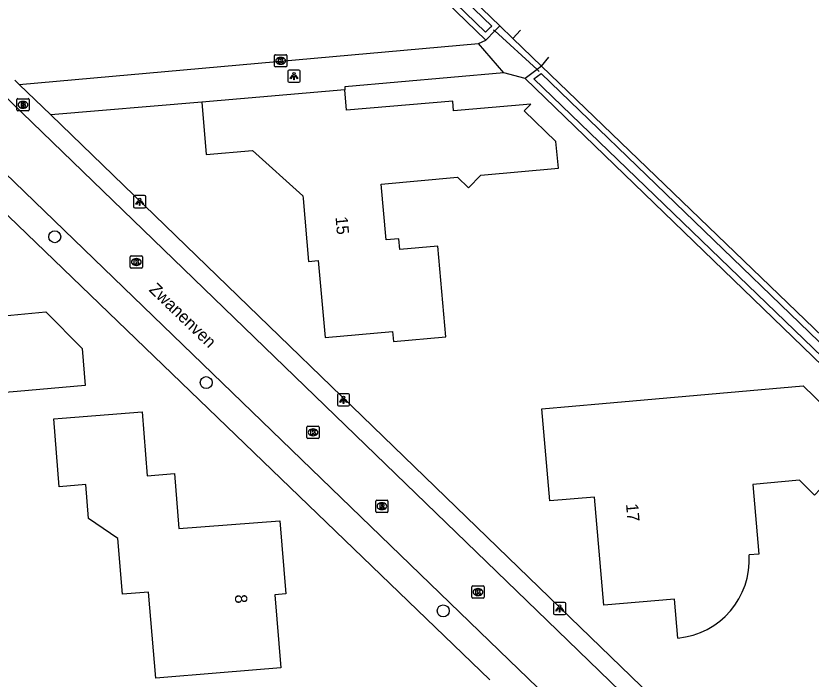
# Model space of a CAD drawing. Extents: x 163427 to 164190, y 380331 to 381641.
# Drawn here: x 164069.2 to 164134.4, y 381117.1 to 381171.6 of the extents above; entities that cross this region are included whole.
import ezdxf

# ---------------------------------------------------------------- set-up
doc = ezdxf.new("R2010")
doc.units = 0
for name, color, linetype in [('IMGEO_Boom', 7, 'Continuous'), ('IMGEO_Brandkraan', 7, 'Continuous'), ('IMGEO_Duiker', 7, 'Continuous'), ('IMGEO_Erf', 7, 'Continuous'), ('IMGEO_Grasland_overig', 7, 'Continuous'), ('IMGEO_Groenvoorziening', 7, 'Continuous'), ('IMGEO_Kolk', 7, 'Continuous'), ('IMGEO_Lichtpunt', 7, 'Continuous'), ('IMGEO_Openbare_ruimte_label', 7, 'Continuous'), ('IMGEO_Pand', 7, 'Continuous'), ('IMGEO_Pand_nummerreeks', 7, 'Continuous'), ('IMGEO_Rijbaan_lokaal_open', 7, 'Continuous'), ('IMGEO_Rioolput', 7, 'Continuous'), ('IMGEO_Voetpad_open', 7, 'Continuous'), ('IMGEO_Waterloop', 7, 'Continuous')]:
    doc.layers.add(name, color=color, linetype=linetype)

msp = doc.modelspace()

# ---------------------------------------------------------------- linework, layer by layer
at = {"layer": 'IMGEO_Boom'}
for centre in [(164072.345, 381153.442), (164084.77, 381141.476), (164104.218, 381122.747)]:
    msp.add_circle(centre, 0.489, dxfattribs=at)
at = {"layer": 'IMGEO_Brandkraan'}
for p, q in [((164069.234, 381163.847), (164069.234, 381164.699)), ((164069.309, 381164.773), (164070.161, 381164.773)), ((164069.722, 381164.553), (164069.747, 381164.553)), ((164070.235, 381164.699), (164070.235, 381163.847)), ((164070.161, 381163.773), (164069.309, 381163.773)), ((164069.745, 381163.993), (164069.72, 381163.993))]:
    msp.add_line(p, q, dxfattribs=at)
for points in [[(164069.234, 381163.847), (164069.234, 381164.699)], [(164069.309, 381164.773), (164070.161, 381164.773)], [(164069.582, 381164.473), (164069.582, 381164.073), (164069.795, 381164.073)], [(164069.813, 381164.473), (164069.582, 381164.473)], [(164069.761, 381164.392), (164069.707, 381164.392), (164069.707, 381164.316)], [(164070.235, 381164.699), (164070.235, 381163.847)], [(164070.161, 381163.773), (164069.309, 381163.773)], [(164069.707, 381164.316), (164069.76, 381164.316)], [(164069.769, 381164.24), (164069.707, 381164.24), (164069.707, 381164.159)], [(164069.707, 381164.159), (164069.769, 381164.159)]]:
    msp.add_lwpolyline(points, dxfattribs=at)
for centre, radius, start, end in [((164069.311, 381164.697), 0.0765, 91.55205, 178.44795), ((164069.311, 381164.697), 0.0765, 91.55205, 178.44795), ((164069.762, 381164.354), 0.0379, 267.82845, 90.93552), ((164069.817, 381164.328), 0.145, 59.4692, 91.53667), ((164069.842, 381164.375), 0.0922, 285.51372, 58.15012), ((164070.159, 381164.697), 0.0765, 1.55205, 88.44795), ((164070.159, 381164.697), 0.0765, 1.55205, 88.44795), ((164069.311, 381163.849), 0.0765, 181.55205, 268.44795), ((164069.311, 381163.849), 0.0765, 181.55205, 268.44795), ((164069.77, 381164.199), 0.0404, 269.87594, 90.50774), ((164069.801, 381164.324), 0.251, 268.66757, 293.53466), ((164069.847, 381164.183), 0.105, 301.31148, 78.98903), ((164070.159, 381163.849), 0.0765, 271.55205, 358.44795), ((164070.159, 381163.849), 0.0765, 271.55205, 358.44795)]:
    msp.add_arc(centre, radius, start, end, dxfattribs=at)
for centre, major_axis, ratio, start_param, end_param in [((164069.721, 381164.273), (-0.387, 0.002), 0.722429, 4.712389, 7.853982), ((164069.746, 381164.273), (-0.39, 0.002), 0.717154, 1.570796, 4.712389)]:
    msp.add_ellipse(centre, major_axis=major_axis, ratio=ratio, start_param=start_param, end_param=end_param, dxfattribs=at)
at = {"layer": 'IMGEO_Duiker'}
msp.add_lwpolyline([(164108.35, 381170.434), (164108.455, 381170.337), (164111.92, 381167.157), (164112.097, 381166.994)], dxfattribs=at)
at = {"layer": 'IMGEO_Erf'}
for points in [[(164107.706, 381169.57), (164048.673, 381226.627)], [(164110.946, 381166.44), (164188.244, 381091.729), (164174.663, 381031.408)]]:
    msp.add_lwpolyline(points, dxfattribs=at)
at = {"layer": 'IMGEO_Grasland_overig'}
for points in [[(164107.706, 381169.57), (164108.455, 381170.337), (164108.853, 381170.745)], [(164108.853, 381170.745), (164109.919, 381169.719)], [(164110.572, 381170.402), (164109.919, 381169.719)], [(164109.919, 381169.719), (164112.295, 381167.433)], [(164107.124, 381169.299), (164107.706, 381169.57)], [(164112.295, 381167.433), (164112.887, 381168.187)], [(164112.295, 381167.433), (164111.92, 381167.157), (164110.946, 381166.44)], [(164110.946, 381166.44), (164109.183, 381166.887)]]:
    msp.add_lwpolyline(points, dxfattribs=at)
at = {"layer": 'IMGEO_Groenvoorziening'}
for points in [[(164047.558, 381229.716), (164108.853, 381170.745)], [(164176.653, 381024.321), (164174.861, 381024.342), (164190.17, 381092.51), (164112.295, 381167.433)]]:
    msp.add_lwpolyline(points, dxfattribs=at)
at = {"layer": 'IMGEO_Kolk'}
for p, q in [((164090.38, 381167.453), (164090.38, 381168.305)), ((164090.455, 381168.379), (164091.307, 381168.379)), ((164091.381, 381168.305), (164091.381, 381167.453)), ((164090.868, 381168.159), (164090.893, 381168.159)), ((164091.307, 381167.379), (164090.455, 381167.379)), ((164090.891, 381167.599), (164090.866, 381167.599)), ((164078.539, 381150.947), (164078.539, 381151.799)), ((164078.614, 381151.873), (164079.466, 381151.873)), ((164079.027, 381151.653), (164079.052, 381151.653)), ((164079.54, 381151.799), (164079.54, 381150.947)), ((164079.466, 381150.873), (164078.614, 381150.873)), ((164079.05, 381151.093), (164079.025, 381151.093)), ((164093.039, 381136.966), (164093.039, 381137.818)), ((164093.114, 381137.892), (164093.966, 381137.892)), ((164093.527, 381137.672), (164093.552, 381137.672)), ((164094.04, 381137.818), (164094.04, 381136.966)), ((164093.55, 381137.112), (164093.525, 381137.112)), ((164093.966, 381136.892), (164093.114, 381136.892)), ((164106.569, 381123.863), (164106.569, 381124.715)), ((164106.644, 381124.789), (164107.496, 381124.789)), ((164107.057, 381124.569), (164107.082, 381124.569)), ((164107.57, 381124.715), (164107.57, 381123.863)), ((164107.08, 381124.009), (164107.055, 381124.009)), ((164107.496, 381123.789), (164106.644, 381123.789))]:
    msp.add_line(p, q, dxfattribs=at)
for points in [[(164090.38, 381167.453), (164090.38, 381168.305)], [(164090.455, 381168.379), (164091.307, 381168.379)], [(164091.381, 381168.305), (164091.381, 381167.453)], [(164090.701, 381168.079), (164090.824, 381168.079), (164090.824, 381167.928), (164090.954, 381168.079), (164091.118, 381168.079), (164090.972, 381167.928), (164091.125, 381167.679), (164090.973, 381167.679), (164090.888, 381167.843), (164090.824, 381167.776), (164090.824, 381167.679), (164090.701, 381167.679), (164090.701, 381168.079)], [(164091.307, 381167.379), (164090.455, 381167.379)], [(164078.539, 381150.947), (164078.539, 381151.799)], [(164078.614, 381151.873), (164079.466, 381151.873)], [(164078.86, 381151.573), (164078.983, 381151.573), (164078.983, 381151.422), (164079.113, 381151.573), (164079.277, 381151.573), (164079.131, 381151.422), (164079.284, 381151.173), (164079.132, 381151.173), (164079.047, 381151.337), (164078.983, 381151.27), (164078.983, 381151.173), (164078.86, 381151.173), (164078.86, 381151.573)], [(164079.54, 381151.799), (164079.54, 381150.947)], [(164079.466, 381150.873), (164078.614, 381150.873)], [(164093.039, 381136.966), (164093.039, 381137.818)], [(164093.114, 381137.892), (164093.966, 381137.892)], [(164094.04, 381137.818), (164094.04, 381136.966)], [(164093.36, 381137.592), (164093.483, 381137.592), (164093.483, 381137.441), (164093.613, 381137.592), (164093.777, 381137.592), (164093.631, 381137.441), (164093.784, 381137.192), (164093.632, 381137.192), (164093.547, 381137.356), (164093.483, 381137.289), (164093.483, 381137.192), (164093.36, 381137.192), (164093.36, 381137.592)], [(164093.966, 381136.892), (164093.114, 381136.892)], [(164106.569, 381123.863), (164106.569, 381124.715)], [(164106.644, 381124.789), (164107.496, 381124.789)], [(164107.57, 381124.715), (164107.57, 381123.863)], [(164106.89, 381124.489), (164107.013, 381124.489), (164107.013, 381124.338), (164107.143, 381124.489), (164107.307, 381124.489), (164107.161, 381124.338), (164107.314, 381124.089), (164107.162, 381124.089), (164107.077, 381124.253), (164107.013, 381124.186), (164107.013, 381124.089), (164106.89, 381124.089), (164106.89, 381124.489)], [(164107.496, 381123.789), (164106.644, 381123.789)]]:
    msp.add_lwpolyline(points, dxfattribs=at)
for centre, start, end in [((164090.457, 381168.303), 91.55205, 178.44795), ((164090.457, 381168.303), 91.55205, 178.44795), ((164091.305, 381168.303), 1.55205, 88.44795), ((164091.305, 381168.303), 1.55205, 88.44795), ((164090.457, 381167.455), 181.55205, 268.44795), ((164090.457, 381167.455), 181.55205, 268.44795), ((164091.305, 381167.455), 271.55205, 358.44795), ((164091.305, 381167.455), 271.55205, 358.44795), ((164078.616, 381151.797), 91.55205, 178.44795), ((164078.616, 381151.797), 91.55205, 178.44795), ((164079.464, 381151.797), 1.55205, 88.44795), ((164079.464, 381151.797), 1.55205, 88.44795), ((164078.616, 381150.949), 181.55205, 268.44795), ((164078.616, 381150.949), 181.55205, 268.44795), ((164079.464, 381150.949), 271.55205, 358.44795), ((164079.464, 381150.949), 271.55205, 358.44795), ((164093.116, 381137.816), 91.55205, 178.44795), ((164093.116, 381137.816), 91.55205, 178.44795), ((164093.964, 381137.816), 1.55205, 88.44795), ((164093.964, 381137.816), 1.55205, 88.44795), ((164093.116, 381136.968), 181.55205, 268.44795), ((164093.116, 381136.968), 181.55205, 268.44795), ((164093.964, 381136.968), 271.55205, 358.44795), ((164093.964, 381136.968), 271.55205, 358.44795), ((164106.646, 381124.713), 91.55205, 178.44795), ((164106.646, 381124.713), 91.55205, 178.44795), ((164107.494, 381124.713), 1.55205, 88.44795), ((164107.494, 381124.713), 1.55205, 88.44795), ((164106.646, 381123.865), 181.55205, 268.44795), ((164106.646, 381123.865), 181.55205, 268.44795), ((164107.494, 381123.865), 271.55205, 358.44795), ((164107.494, 381123.865), 271.55205, 358.44795)]:
    msp.add_arc(centre, 0.0765, start, end, dxfattribs=at)
for centre, major_axis, ratio, start_param, end_param in [((164090.867, 381167.879), (-0.387, 0.002), 0.722429, 4.712389, 7.853982), ((164090.892, 381167.879), (-0.39, 0.002), 0.717154, 1.570796, 4.712389), ((164079.026, 381151.373), (-0.387, 0.002), 0.722429, 4.712389, 7.853982), ((164079.051, 381151.373), (-0.39, 0.002), 0.717154, 1.570796, 4.712389), ((164093.526, 381137.392), (-0.387, 0.002), 0.722429, 4.712389, 7.853982), ((164093.551, 381137.392), (-0.39, 0.002), 0.717154, 1.570796, 4.712389), ((164107.056, 381124.289), (-0.387, 0.002), 0.722429, 4.712389, 7.853982), ((164107.081, 381124.289), (-0.39, 0.002), 0.717154, 1.570796, 4.712389)]:
    msp.add_ellipse(centre, major_axis=major_axis, ratio=ratio, start_param=start_param, end_param=end_param, dxfattribs=at)
at = {"layer": 'IMGEO_Lichtpunt'}
for p, q in [((164091.478, 381167.027), (164091.478, 381166.22)), ((164091.478, 381167.027), (164091.478, 381166.22)), ((164092.38, 381167.122), (164091.572, 381167.122)), ((164092.38, 381167.122), (164091.572, 381167.122)), ((164092.474, 381166.22), (164092.474, 381167.027)), ((164092.474, 381166.22), (164092.474, 381167.027)), ((164091.572, 381166.126), (164092.38, 381166.126)), ((164091.572, 381166.126), (164092.38, 381166.126)), ((164078.813, 381156.722), (164078.813, 381155.915)), ((164078.813, 381156.722), (164078.813, 381155.915)), ((164079.715, 381156.817), (164078.907, 381156.817)), ((164079.715, 381156.817), (164078.907, 381156.817)), ((164079.809, 381155.915), (164079.809, 381156.722)), ((164079.809, 381155.915), (164079.809, 381156.722)), ((164078.907, 381155.821), (164079.715, 381155.821)), ((164078.907, 381155.821), (164079.715, 381155.821)), ((164095.537, 381140.466), (164095.537, 381139.659)), ((164095.537, 381140.466), (164095.537, 381139.659)), ((164096.439, 381140.561), (164095.631, 381140.561)), ((164096.439, 381140.561), (164095.631, 381140.561)), ((164096.533, 381139.659), (164096.533, 381140.466)), ((164096.533, 381139.659), (164096.533, 381140.466)), ((164095.631, 381139.565), (164096.439, 381139.565)), ((164095.631, 381139.565), (164096.439, 381139.565)), ((164113.275, 381123.349), (164113.275, 381122.542)), ((164113.275, 381123.349), (164113.275, 381122.542)), ((164114.177, 381123.444), (164113.369, 381123.444)), ((164114.177, 381123.444), (164113.369, 381123.444)), ((164114.271, 381122.542), (164114.271, 381123.349)), ((164114.271, 381122.542), (164114.271, 381123.349)), ((164113.369, 381122.448), (164114.177, 381122.448)), ((164113.369, 381122.448), (164114.177, 381122.448))]:
    msp.add_line(p, q, dxfattribs=at)
for points in [[(164091.852, 381166.691), (164091.891, 381166.663), (164091.703, 381166.401), (164091.665, 381166.428), (164091.852, 381166.691)], [(164091.954, 381166.643), (164092.001, 381166.643), (164092.001, 381166.321), (164091.954, 381166.321), (164091.954, 381166.643)], [(164092.064, 381166.663), (164092.102, 381166.69), (164092.289, 381166.428), (164092.25, 381166.4), (164092.064, 381166.663)], [(164079.187, 381156.386), (164079.226, 381156.358), (164079.038, 381156.096), (164079, 381156.123), (164079.187, 381156.386)], [(164079.289, 381156.338), (164079.336, 381156.338), (164079.336, 381156.016), (164079.289, 381156.016), (164079.289, 381156.338)], [(164079.399, 381156.358), (164079.437, 381156.385), (164079.624, 381156.123), (164079.585, 381156.095), (164079.399, 381156.358)], [(164095.911, 381140.13), (164095.95, 381140.102), (164095.762, 381139.84), (164095.724, 381139.867), (164095.911, 381140.13)], [(164096.013, 381140.082), (164096.06, 381140.082), (164096.06, 381139.76), (164096.013, 381139.76), (164096.013, 381140.082)], [(164096.123, 381140.102), (164096.161, 381140.129), (164096.348, 381139.867), (164096.309, 381139.839), (164096.123, 381140.102)], [(164113.649, 381123.013), (164113.688, 381122.985), (164113.5, 381122.723), (164113.462, 381122.75), (164113.649, 381123.013)], [(164113.751, 381122.965), (164113.798, 381122.965), (164113.798, 381122.643), (164113.751, 381122.643), (164113.751, 381122.965)], [(164113.861, 381122.985), (164113.899, 381123.012), (164114.086, 381122.75), (164114.047, 381122.722), (164113.861, 381122.985)]]:
    msp.add_lwpolyline(points, dxfattribs=at)
for centre in [(164091.977, 381166.825), (164079.312, 381156.52), (164096.036, 381140.264), (164113.774, 381123.147)]:
    msp.add_circle(centre, 0.0994, dxfattribs=at)
for centre, start, end in [((164091.572, 381167.027), 90, 180), ((164091.572, 381167.027), 90, 180), ((164092.38, 381167.027), 0, 90), ((164092.38, 381167.027), 0, 90), ((164091.572, 381166.22), 180, 270), ((164091.572, 381166.22), 180, 270), ((164092.38, 381166.22), 270, 0), ((164092.38, 381166.22), 270, 360), ((164078.907, 381156.722), 90, 180), ((164078.907, 381156.722), 90, 180), ((164079.715, 381156.722), 0, 90), ((164079.715, 381156.722), 0, 90), ((164078.907, 381155.915), 180, 270), ((164078.907, 381155.915), 180, 270), ((164079.715, 381155.915), 270, 0), ((164079.715, 381155.915), 270, 360), ((164095.631, 381140.466), 90, 180), ((164095.631, 381140.466), 90, 180), ((164096.439, 381140.466), 0, 90), ((164096.439, 381140.466), 0, 90), ((164095.631, 381139.659), 180, 270), ((164095.631, 381139.659), 180, 270), ((164096.439, 381139.659), 270, 0), ((164096.439, 381139.659), 270, 360), ((164113.369, 381123.349), 90, 180), ((164113.369, 381123.349), 90, 180), ((164114.177, 381123.349), 0, 90), ((164114.177, 381123.349), 0, 90), ((164113.369, 381122.542), 180, 270), ((164113.369, 381122.542), 180, 270), ((164114.177, 381122.542), 270, 0), ((164114.177, 381122.542), 270, 360)]:
    msp.add_arc(centre, 0.0946, start, end, dxfattribs=at)
at = {"layer": 'IMGEO_Pand'}
for points in [[(164084.403, 381164.489), (164084.768, 381160.201), (164088.564, 381160.518), (164092.696, 381156.812), (164092.716, 381156.581), (164093.169, 381151.403), (164093.966, 381151.493), (164094.536, 381145.169), (164100.06, 381145.663), (164100.133, 381144.847), (164104.442, 381145.233), (164103.777, 381152.667), (164100.662, 381152.389), (164100.582, 381153.284), (164099.527, 381153.19), (164099.117, 381157.768), (164105.392, 381158.329), (164106.302, 381157.443), (164107.294, 381158.5), (164113.668, 381159.07), (164113.472, 381161.245), (164110.871, 381163.771), (164111.404, 381164.32), (164105.074, 381163.772), (164105.005, 381164.568), (164096.283, 381163.823), (164096.139, 381165.508)], [(164096.139, 381165.508), (164084.403, 381164.489)], [(164060.198, 381139.979), (164059.545, 381147.634), (164058.45, 381147.541), (164055.911, 381147.325), (164055.547, 381151.068), (164055.113, 381155.531), (164063.805, 381156.377), (164064.151, 381152.826), (164066.921, 381153.095), (164067.516, 381146.905), (164068.726, 381147.015), (164071.62, 381147.278), (164074.58, 381144.286), (164074.84, 381141.227), (164069.26, 381140.751), (164060.198, 381139.979)], [(164123.469, 381120.518), (164123.186, 381123.719), (164117.41, 381123.208), (164116.635, 381132.084), (164112.964, 381131.763), (164112.304, 381139.326), (164117.286, 381139.761), (164133.767, 381141.199), (164139.445, 381135.681), (164135.905, 381132.01), (164135.145, 381132.718), (164134.693, 381132.233), (164133.458, 381133.465)], [(164080.645, 381117.217), (164080.048, 381124.292), (164077.906, 381124.111), (164077.52, 381128.696), (164075.103, 381130.312), (164074.88, 381133.102), (164072.705, 381132.928), (164072.259, 381138.51), (164072.939, 381138.564), (164079.515, 381139.089), (164079.913, 381133.834), (164082.175, 381134.004), (164082.517, 381129.491), (164090.822, 381130.12), (164091.311, 381124.151), (164090.402, 381124.074), (164090.908, 381118.083), (164085.926, 381117.662), (164080.645, 381117.217)], [(164133.458, 381133.465), (164129.612, 381133.123), (164130.121, 381127.409), (164129.313, 381127.338)]]:
    msp.add_lwpolyline(points, dxfattribs=at)
msp.add_arc((164122.905, 381126.915), 6.422, 275.03496, 3.77906, dxfattribs=at)
at = {"layer": 'IMGEO_Rijbaan_lokaal_open'}
for points in [[(164068.014, 381165.227), (164112.746, 381121.956), (164141.941, 381093.714)], [(164138.201, 381091.126), (164109.62, 381118.71), (164064.951, 381161.82)]]:
    msp.add_lwpolyline(points, dxfattribs=at)
at = {"layer": 'IMGEO_Rioolput'}
for p, q in [((164098.686, 381130.903), (164098.686, 381131.755)), ((164098.761, 381131.829), (164099.613, 381131.829)), ((164099.687, 381131.755), (164099.687, 381130.903)), ((164099.174, 381131.609), (164099.199, 381131.609)), ((164099.613, 381130.829), (164098.761, 381130.829)), ((164099.197, 381131.049), (164099.172, 381131.049))]:
    msp.add_line(p, q, dxfattribs=at)
for points in [[(164098.686, 381130.903), (164098.686, 381131.755)], [(164098.761, 381131.829), (164099.613, 381131.829)], [(164099.687, 381131.755), (164099.687, 381130.903)], [(164099.275, 381131.527), (164099.023, 381131.529), (164099.023, 381131.129)], [(164099.023, 381131.129), (164099.147, 381131.129), (164099.147, 381131.291), (164099.158, 381131.291)], [(164099.201, 381131.448), (164099.147, 381131.448), (164099.147, 381131.367)], [(164099.147, 381131.367), (164099.199, 381131.367)], [(164099.205, 381131.262), (164099.276, 381131.129), (164099.416, 381131.129), (164099.351, 381131.255)], [(164099.613, 381130.829), (164098.761, 381130.829)]]:
    msp.add_lwpolyline(points, dxfattribs=at)
for centre, radius, start, end in [((164098.763, 381131.753), 0.0765, 91.55205, 178.44795), ((164098.763, 381131.753), 0.0765, 91.55205, 178.44795), ((164099.611, 381131.753), 0.0765, 1.55205, 88.44795), ((164099.611, 381131.753), 0.0765, 1.55205, 88.44795), ((164099.157, 381131.238), 0.0533, 26.02933, 88.69889), ((164099.183, 381131.556), 0.19, 274.7715, 282.96867), ((164099.207, 381131.352), 0.0964, 77.00612, 93.18647), ((164099.221, 381131.409), 0.0378, 276.66336, 79.67722), ((164099.274, 381131.417), 0.109, 350.36119, 89.41601), ((164099.272, 381131.417), 0.112, 277.58423, 350.98172), ((164099.256, 381131.202), 0.108, 29.51342, 73.79051), ((164098.763, 381130.905), 0.0765, 181.55205, 268.44795), ((164098.763, 381130.905), 0.0765, 181.55205, 268.44795), ((164099.611, 381130.905), 0.0765, 271.55205, 358.44795), ((164099.611, 381130.905), 0.0765, 271.55205, 358.44795)]:
    msp.add_arc(centre, radius, start, end, dxfattribs=at)
for centre, major_axis, ratio, start_param, end_param in [((164099.173, 381131.329), (-0.387, 0.002), 0.722429, 4.712389, 7.853982), ((164099.198, 381131.329), (-0.39, 0.002), 0.717154, 1.570796, 4.712389)]:
    msp.add_ellipse(centre, major_axis=major_axis, ratio=ratio, start_param=start_param, end_param=end_param, dxfattribs=at)
at = {"layer": 'IMGEO_Voetpad_open'}
for points in [[(164069.43, 381165.933), (164107.124, 381169.299)], [(164109.183, 381166.887), (164107.124, 381169.299)], [(164109.183, 381166.887), (164096.151, 381165.734), (164096.139, 381165.508)], [(164069.076, 381166.296), (164069.43, 381165.933)], [(164072.028, 381163.438), (164069.43, 381165.933)], [(164084.403, 381164.489), (164072.028, 381163.438)], [(164142.972, 381094.786), (164113.783, 381123.032), (164072.028, 381163.438)], [(164108.047, 381117.077), (164063.324, 381160.15)]]:
    msp.add_lwpolyline(points, dxfattribs=at)
at = {"layer": 'IMGEO_Waterloop'}
for points in [[(164047.44, 381229.194), (164029.714, 381223.306), (164029.801, 381223.031), (164030.086, 381222.129), (164048.149, 381227.771), (164048.992, 381226.957), (164107.697, 381170.217), (164108.127, 381170.657), (164108.202, 381170.735), (164047.44, 381229.194)], [(164138.395, 381023.165), (164138.446, 381023.249), (164138.525, 381023.304), (164138.628, 381023.343), (164138.749, 381023.37), (164139.021, 381023.404), (164172.643, 381022.5), (164173.269, 381022.93), (164175.152, 381031.298), (164188.795, 381091.894), (164140.313, 381138.753), (164135.67, 381143.24), (164135.339, 381143.56), (164111.657, 381166.392), (164112.255, 381166.833), (164135.844, 381144.082), (164136.175, 381143.762), (164140.828, 381139.286), (164189.619, 381092.344), (164174.272, 381024.006)]]:
    msp.add_lwpolyline(points, dxfattribs=at)

# ---------------------------------------------------------------- texts
at = {"layer": 'IMGEO_Openbare_ruimte_label'}
msp.add_text('Zwanenven', height=1, rotation=316.13442, dxfattribs=at).set_placement((164080.012, 381149.034))
at = {"layer": 'IMGEO_Pand_nummerreeks'}
for s, rotation, p in [('15', 274.99762, (164095.379, 381155.06)), ('17', 274.99025, (164119.214, 381131.509)), ('8', 274.82774, (164087.112, 381124.058))]:
    msp.add_text(s, height=1, rotation=rotation, dxfattribs=at).set_placement(p)

doc.saveas('drawing.dxf')
